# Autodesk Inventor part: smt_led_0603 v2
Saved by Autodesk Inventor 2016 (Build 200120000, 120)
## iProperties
Created: 2016-09
Part Number: smt_led_0603 v2
Material: Generic
Document SubType Name: Modeling
Designer: Administrator
Appearance: Generic
Author: Administrator
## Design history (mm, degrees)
feature "Body1"
feature "Body2"
feature "Body3"
feature "Body4"
feature "Body5"
feature "Body6"
feature "Body8"
body "Solid1"
body "Solid2"
body "Solid3"
body "Solid4"
body "Solid5"
body "Solid6"
body "Solid7"
